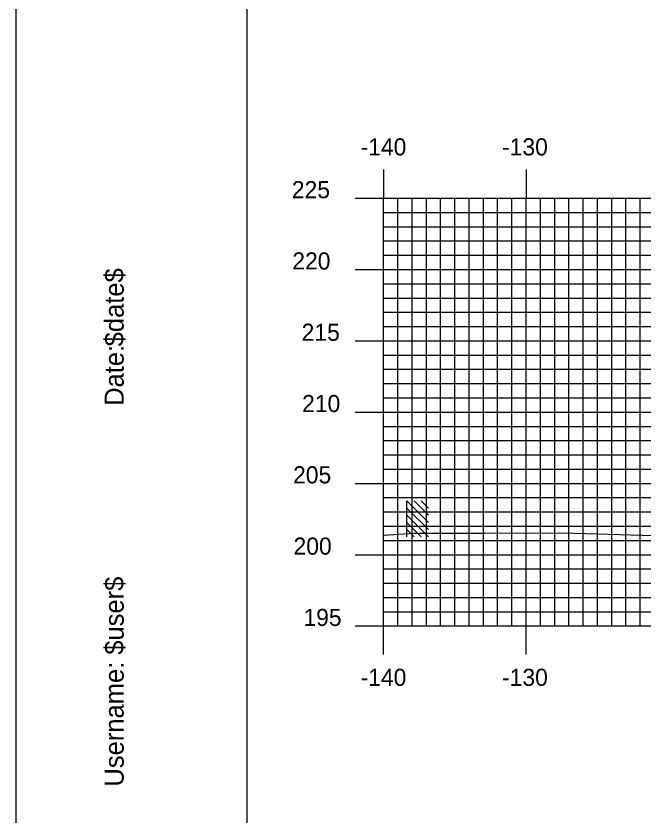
# Model space of a CAD drawing. Extents: x 852529 to 852872, y 364785 to 365005.
# Drawn here: x 852528.9 to 852572.9, y 364892.9 to 364949 of the extents above; entities that cross this region are included whole.
import ezdxf

# ---------------------------------------------------------------- set-up
doc = ezdxf.new("R2010")
doc.units = 0
for name, color, linetype in [('BORDER', 7, 'Continuous'), ('H_V ANNOTATION', 7, 'Continuous'), ('M_Buildings_Rooftop', 7, 'Continuous'), ('MAJOR', 7, 'Continuous'), ('MINOR', 7, 'Continuous'), ('PLOT BOUNDARY', 7, 'Continuous'), ('S_Roadway_Centerline', 7, 'Continuous')]:
    doc.layers.add(name, color=color, linetype=linetype)

msp = doc.modelspace()

# ---------------------------------------------------------------- linework, layer by layer
at = {"layer": 'BORDER'}
msp.add_lwpolyline([(852545.131, 364791.233), (852865.131, 364791.233), (852865.131, 365001.233), (852545.131, 365001.233)], close=True, dxfattribs=at)
at = {"layer": 'M_Buildings_Rooftop'}
for p, q in [((852556.359, 364912.484), (852556.359, 364915.01)), ((852557.868, 364913.501), (852556.359, 364915.01)), ((852557.868, 364913.993), (852556.884, 364915.01)), ((852557.868, 364914.485), (852557.376, 364915.01)), ((852557.868, 364913.009), (852556.359, 364914.485)), ((852557.868, 364912.484), (852556.359, 364913.993)), ((852557.376, 364912.484), (852556.359, 364913.501)), ((852556.884, 364912.484), (852556.359, 364913.009))]:
    msp.add_line(p, q, dxfattribs=at)
at = {"layer": 'MAJOR'}
for p, q in [((852554.731, 364938.237), (852554.731, 364936.233)), ((852564.731, 364938.237), (852564.731, 364936.233)), ((852552.727, 364936.233), (852554.731, 364936.233)), ((852554.731, 364936.233), (852834.731, 364936.233)), ((852554.731, 364906.233), (852554.731, 364936.233)), ((852554.731, 364906.233), (852554.731, 364936.233)), ((852554.731, 364936.233), (852834.731, 364936.233)), ((852564.731, 364906.233), (852564.731, 364936.233)), ((852552.727, 364931.233), (852554.731, 364931.233)), ((852554.731, 364931.233), (852834.731, 364931.233)), ((852552.727, 364926.233), (852554.731, 364926.233)), ((852554.731, 364926.233), (852834.731, 364926.233)), ((852552.727, 364921.233), (852554.731, 364921.233)), ((852554.731, 364921.233), (852834.731, 364921.233)), ((852552.727, 364916.233), (852554.731, 364916.233)), ((852554.731, 364916.233), (852834.731, 364916.233)), ((852552.727, 364911.233), (852554.731, 364911.233)), ((852554.731, 364911.233), (852834.731, 364911.233)), ((852552.727, 364906.233), (852554.731, 364906.233)), ((852554.731, 364906.233), (852834.731, 364906.233)), ((852554.731, 364906.233), (852834.731, 364906.233)), ((852554.731, 364904.229), (852554.731, 364906.233)), ((852564.731, 364904.229), (852564.731, 364906.233))]:
    msp.add_line(p, q, dxfattribs=at)
at = {"layer": 'MINOR'}
for p, q in [((852555.731, 364906.233), (852555.731, 364936.233)), ((852556.731, 364906.233), (852556.731, 364936.233)), ((852557.731, 364906.233), (852557.731, 364936.233)), ((852558.731, 364906.233), (852558.731, 364936.233)), ((852559.731, 364906.233), (852559.731, 364936.233)), ((852560.731, 364906.233), (852560.731, 364936.233)), ((852561.731, 364906.233), (852561.731, 364936.233)), ((852562.731, 364906.233), (852562.731, 364936.233)), ((852563.731, 364906.233), (852563.731, 364936.233)), ((852565.731, 364906.233), (852565.731, 364936.233)), ((852566.731, 364906.233), (852566.731, 364936.233)), ((852567.731, 364906.233), (852567.731, 364936.233)), ((852568.731, 364906.233), (852568.731, 364936.233)), ((852569.731, 364906.233), (852569.731, 364936.233)), ((852570.731, 364906.233), (852570.731, 364936.233)), ((852571.731, 364906.233), (852571.731, 364936.233)), ((852572.731, 364906.233), (852572.731, 364936.233)), ((852554.731, 364935.233), (852834.731, 364935.233)), ((852554.731, 364935.233), (852556.735, 364935.233)), ((852554.731, 364934.233), (852834.731, 364934.233)), ((852554.731, 364934.233), (852556.735, 364934.233)), ((852554.731, 364933.233), (852834.731, 364933.233)), ((852554.731, 364933.233), (852556.735, 364933.233)), ((852554.731, 364932.233), (852834.731, 364932.233)), ((852554.731, 364932.233), (852556.735, 364932.233)), ((852554.731, 364930.233), (852834.731, 364930.233)), ((852554.731, 364930.233), (852556.735, 364930.233)), ((852554.731, 364929.233), (852834.731, 364929.233)), ((852554.731, 364929.233), (852556.735, 364929.233)), ((852554.731, 364928.233), (852834.731, 364928.233)), ((852554.731, 364928.233), (852556.735, 364928.233)), ((852554.731, 364927.233), (852834.731, 364927.233)), ((852554.731, 364927.233), (852556.735, 364927.233)), ((852554.731, 364925.233), (852834.731, 364925.233)), ((852554.731, 364925.233), (852556.735, 364925.233)), ((852554.731, 364924.233), (852834.731, 364924.233)), ((852554.731, 364924.233), (852556.735, 364924.233)), ((852554.731, 364923.233), (852834.731, 364923.233)), ((852554.731, 364923.233), (852556.735, 364923.233)), ((852554.731, 364922.233), (852834.731, 364922.233)), ((852554.731, 364922.233), (852556.735, 364922.233)), ((852554.731, 364920.233), (852834.731, 364920.233)), ((852554.731, 364920.233), (852556.735, 364920.233)), ((852554.731, 364919.233), (852834.731, 364919.233)), ((852554.731, 364919.233), (852556.735, 364919.233)), ((852554.731, 364918.233), (852834.731, 364918.233)), ((852554.731, 364918.233), (852556.735, 364918.233)), ((852554.731, 364917.233), (852834.731, 364917.233)), ((852554.731, 364917.233), (852556.735, 364917.233)), ((852554.731, 364915.233), (852834.731, 364915.233)), ((852554.731, 364915.233), (852556.735, 364915.233)), ((852554.731, 364914.233), (852834.731, 364914.233)), ((852554.731, 364914.233), (852556.735, 364914.233)), ((852554.731, 364913.233), (852834.731, 364913.233)), ((852554.731, 364913.233), (852556.735, 364913.233)), ((852554.731, 364912.233), (852834.731, 364912.233)), ((852554.731, 364912.233), (852556.735, 364912.233)), ((852554.731, 364910.233), (852834.731, 364910.233)), ((852554.731, 364910.233), (852556.735, 364910.233)), ((852554.731, 364909.233), (852834.731, 364909.233)), ((852554.731, 364909.233), (852556.735, 364909.233)), ((852554.731, 364908.233), (852834.731, 364908.233)), ((852554.731, 364908.233), (852556.735, 364908.233)), ((852554.731, 364907.233), (852834.731, 364907.233)), ((852554.731, 364907.233), (852556.735, 364907.233))]:
    msp.add_line(p, q, dxfattribs=at)
at = {"layer": 'PLOT BOUNDARY'}
msp.add_lwpolyline([(852528.944, 364785.114), (852868.944, 364785.114), (852868.944, 365005.114), (852528.944, 365005.114)], close=True, dxfattribs=at)
at = {"layer": 'S_Roadway_Centerline'}
msp.add_lwpolyline([(852554.731, 364912.608), (852556.867, 364912.747), (852561.877, 364912.743), (852567.317, 364912.767), (852579.975, 364912.389), (852580.113, 364912.383), (852580.931, 364912.389), (852594.428, 364912.451), (852595.268, 364912.427), (852599.382, 364912.425), (852602.093, 364912.479), (852605.312, 364912.513), (852608.626, 364912.935), (852609.06, 364912.976), (852610.613, 364913.393), (852623.858, 364916.427)], dxfattribs=at)

# ---------------------------------------------------------------- texts
at = {"layer": 'BORDER'}
for s, p in [('$date$', (852536.5, 364925.843)), ('Date:', (852536.5, 364921.666)), ('$user$', (852536.5, 364904.216)), ('Username:', (852536.5, 364894.968))]:
    msp.add_text(s, height=1.3392, rotation=90, dxfattribs=at).set_placement(p)
at = {"layer": 'H_V ANNOTATION'}
for s, p in [('-140', (852553.115, 364939.233)), ('-130', (852563.04, 364939.233)), ('225', (852548.294, 364936.233)), ('220', (852548.326, 364931.233)), ('215', (852548.98, 364926.233)), ('210', (852549.012, 364921.233)), ('205', (852548.38, 364916.233)), ('200', (852548.412, 364911.233)), ('195', (852549.108, 364906.233)), ('-140', (852553.115, 364902.033)), ('-130', (852563.04, 364902.033))]:
    msp.add_text(s, height=1.2, dxfattribs=at).set_placement(p)
at = {"layer": 'MAJOR'}
msp.add_text('-', height=0.012, dxfattribs=at).set_placement((852554.722, 364906.233))

doc.saveas('drawing.dxf')
